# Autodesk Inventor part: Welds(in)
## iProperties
Author: Wm.J.Townsend
Created: 2002-03
Part Number: Welds(in)
Document SubType Name: Modeling
Designer: Wm.J.Townsend
Length Units: 11272
Angle Units: 11284
Time Units: 11279
Mass Units: 11290
Length Display Precision: 3
Angle Display Precision: 1
Compacted: False
PropertySet Name: _Private Model Information
Control State: 0
Master: False
Checked Out: False
PropertySet Name: Design Tracking Control
